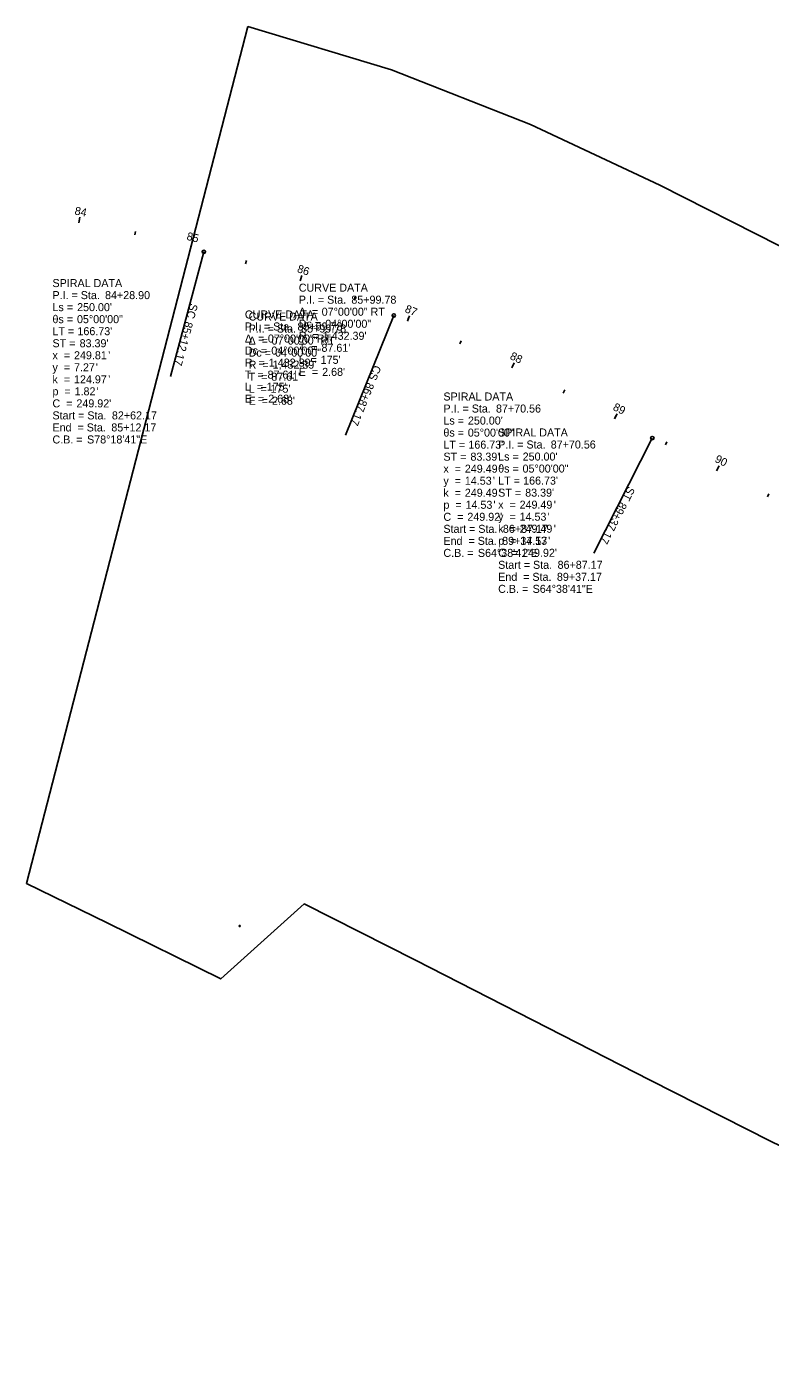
# Model space of a CAD drawing. Extents: x 1999328 to 2003366, y 252318 to 253988.
# Drawn here: x 2001058 to 2001707, y 252318 to 253475 of the extents above; entities that cross this region are included whole.
import ezdxf

# ---------------------------------------------------------------- set-up
doc = ezdxf.new("R2010")
doc.units = 0
for name, color, linetype in [('GE_P_Alignment_500_Stations', 7, 'Continuous'), ('GE_X_Alignment_100_Stations', 7, 'Continuous'), ('RW_X_Esmt_CH', 7, 'Continuous'), ('SC_Scratch3', 7, 'Continuous'), ('SV_X_Mon_Cells_Found', 7, 'Continuous'), ('TX_P_50', 7, 'Continuous'), ('TX_X_20', 7, 'Continuous'), ('TX_X_50', 7, 'Continuous')]:
    doc.layers.add(name, color=color, linetype=linetype)

msp = doc.modelspace()

# ---------------------------------------------------------------- linework, layer by layer
at = {"layer": 'GE_P_Alignment_500_Stations'}
for p, q in [((2001103.3, 253304.2), (2001104.3, 253309.1)), ((2001152.2, 253293.6), (2001152.9, 253296.6)), ((2001212.6, 253278.7), (2001183.4, 253170.1)), ((2001200.8, 253281.8), (2001202.1, 253286.7)), ((2001249, 253268.4), (2001249.8, 253271.3)), ((2001296.6, 253253.4), (2001298.2, 253258.1)), ((2001343.8, 253236.7), (2001344.8, 253239.5)), ((2001378.4, 253223.2), (2001336.2, 253118.9)), ((2001390.3, 253218.3), (2001392.2, 253222.9)), ((2001436.2, 253198.5), (2001437.4, 253201.2)), ((2001481.5, 253177.4), (2001483.7, 253181.9)), ((2001526.4, 253155.5), (2001527.8, 253158.2)), ((2001571.1, 253133), (2001573.4, 253137.5)), ((2001604.2, 253116.2), (2001553.1, 253015.9)), ((2001615.7, 253110.3), (2001617, 253113)), ((2001660.2, 253087.6), (2001662.5, 253092.1)), ((2001704.7, 253064.9), (2001706.1, 253067.6))]:
    msp.add_line(p, q, dxfattribs=at)
for centre in [(2001212.6, 253278.7), (2001378.4, 253223.2), (2001604.2, 253116.2)]:
    msp.add_circle(centre, 1.5, dxfattribs=at)
at = {"layer": 'RW_X_Esmt_CH'}
msp.add_lwpolyline([(2001251, 253475.4), (2001057.7, 252727.4), (2001128.3, 252693.2), (2001227.4, 252644.1), (2001300.1, 252709.6), (2001397.4, 252660.4), (2001499.9, 252608.1), (2001602.3, 252555.9), (2001707.3, 252502.5), (2001828.3, 252444.1), (2001968.2, 252386.2), (2002115.7, 252338.2), (2002180.2, 252318.1), (2002346.8, 253001.2), (2002305.2, 253012.1), (2002211.1, 253042.7), (2002118.4, 253081.1), (2002021.8, 253127.8), (2001920.3, 253179.5), (2001817.9, 253231.7), (2001715.4, 253283.9), (2001610.7, 253336.9), (2001497.9, 253389.8), (2001376.4, 253437.5)], close=True, dxfattribs=at)
at = {"layer": 'SV_X_Mon_Cells_Found'}
for p, q in [((2001212.6, 253278.7), (2001183.4, 253170.1)), ((2001200.8, 253281.8), (2001201.5, 253284.7)), ((2001378.4, 253223.2), (2001336.2, 253118.9)), ((2001604.2, 253116.2), (2001553.1, 253015.9)), ((2001660.2, 253087.6), (2001662.5, 253092.1))]:
    msp.add_line(p, q, dxfattribs=at)
for centre in [(2001212.6, 253278.7), (2001378.4, 253223.2), (2001604.2, 253116.2)]:
    msp.add_circle(centre, 1.5, dxfattribs=at)
at = {"layer": 'TX_P_50'}
for p, q in [((2001103.3, 253304.2), (2001103.9, 253307.1)), ((2001212.6, 253278.7), (2001183.4, 253170.1)), ((2001200.8, 253281.8), (2001202.1, 253286.7)), ((2001296.6, 253253.4), (2001297.6, 253256.2)), ((2001378.4, 253223.2), (2001336.2, 253118.9)), ((2001390.3, 253218.3), (2001391.4, 253221.1)), ((2001481.5, 253177.4), (2001482.8, 253180.1)), ((2001571.1, 253133), (2001572.5, 253135.7)), ((2001604.2, 253116.2), (2001553.1, 253015.9)), ((2001660.2, 253087.6), (2001662.5, 253092.1))]:
    msp.add_line(p, q, dxfattribs=at)
for centre in [(2001212.6, 253278.7), (2001378.4, 253223.2), (2001604.2, 253116.2)]:
    msp.add_circle(centre, 1.5, dxfattribs=at)
at = {"layer": 'TX_X_20'}
msp.add_circle((2001243.9, 252690.3), 0.5, dxfattribs=at)
msp.add_circle((2001243.9, 252690.3), 0.5, dxfattribs=at)

# ---------------------------------------------------------------- texts
at = {"layer": 'GE_P_Alignment_500_Stations'}
for s, rotation, p in [('84', 348.4583, (2001099.3, 253311.5)), ('85', 345.4529, (2001197.1, 253289.4)), ('86', 341.4648, (2001293.5, 253261.2)), ('SC', 254.9781, (2001200.7, 253234.1)), ('87', 337.4779, (2001387.5, 253226.4)), ('85+12.17', 254.9781, (2001196.5, 253218.4)), ('88', 334.4833, (2001479.3, 253185.5)), ('CS', 247.9781, (2001361.2, 253180.4)), ('86+87.17', 247.9781, (2001355.1, 253165.3)), ('89', 333.0886, (2001569.2, 253141.1)), ('90', 332.9781, (2001658.2, 253095.8)), ('ST', 242.9781, (2001583.1, 253074.5)), ('89+37.17', 242.9781, (2001576.2, 253061))]:
    msp.add_text(s, height=7, rotation=rotation, dxfattribs=at).set_placement(p)
at = {"layer": 'GE_X_Alignment_100_Stations'}
for s, p in [('SPIRAL DATA', (2001080.4, 253248)), ('P.I. = Sta. ', (2001080.4, 253237.5)), ('84+28.90', (2001126.3, 253237.5)), ('Ls = ', (2001080.4, 253227)), ("250.00'", (2001101.9, 253227)), ('θs = ', (2001080.4, 253216.5)), ('05°00\'00"', (2001101.8, 253216.5)), ('CURVE DATA', (2001251.7, 253218.8)), ('LT = ', (2001080.4, 253206)), ("166.73'", (2001102.2, 253206)), ('P.I. = Sta. ', (2001251.7, 253208.3)), ('85+99.78', (2001297.6, 253208.3)), ('ST = ', (2001080.4, 253195.5)), ("83.39'", (2001104.1, 253195.5)), ('Δ  = ', (2001251.7, 253197.8)), ('07°00\'00" RT', (2001271.7, 253197.8)), ('x  = ', (2001080.4, 253185)), ('249.81', (2001099.2, 253185)), ("'", (2001129.1, 253185)), ('Dc = ', (2001251.7, 253187.3)), ('04°00\'00"', (2001274.8, 253187.3)), ('y  = ', (2001080.4, 253174.5)), ('7.27', (2001099.2, 253174.5)), ("'", (2001118.2, 253174.5)), ('T  = ', (2001251.7, 253166.3)), ('R  = ', (2001251.7, 253176.8)), ("87.61'", (2001271.5, 253166.3)), ("1,432.39'", (2001272.6, 253176.8)), ('k  = ', (2001080.4, 253164)), ('124.97', (2001099.2, 253164)), ("'", (2001129.1, 253164)), ('L  = ', (2001251.7, 253155.8)), ("175'", (2001270.8, 253155.8)), ('C  = ', (2001080.4, 253143)), ('p  = ', (2001080.4, 253153.5)), ('1.82', (2001099.7, 253153.5)), ("249.92'", (2001101.3, 253143)), ("'", (2001118.7, 253153.5)), ('E  = ', (2001251.7, 253145.3)), ("2.68'", (2001272.1, 253145.3)), ('Start = Sta. ', (2001080.4, 253132.5)), ('82+62.17', (2001132.3, 253132.5)), ('End  = Sta. ', (2001080.4, 253122)), ('85+12.17', (2001131.8, 253122)), ('C.B. = ', (2001080.4, 253111.5)), ('S78°18\'41"E', (2001110.6, 253111.5)), ('SPIRAL DATA', (2001469.6, 253117.6)), ('P.I. = Sta. ', (2001469.6, 253107.1)), ('Ls = ', (2001469.6, 253096.6)), ("250.00'", (2001491, 253096.6)), ('87+70.56', (2001515.5, 253107.1)), ('θs = ', (2001469.6, 253086.1)), ('05°00\'00"', (2001490.9, 253086.1)), ('LT = ', (2001469.6, 253075.6)), ("166.73'", (2001491.4, 253075.6)), ('ST = ', (2001469.6, 253065.1)), ("83.39'", (2001493.2, 253065.1)), ('x  = ', (2001469.6, 253054.6)), ('249.49', (2001488.3, 253054.6)), ("'", (2001518.2, 253054.6)), ('y  = ', (2001469.6, 253044.1)), ('14.53', (2001488.3, 253044.1)), ("'", (2001512.8, 253044.1)), ('k  = ', (2001469.6, 253033.6)), ('249.49', (2001488.3, 253033.6)), ("'", (2001518.2, 253033.6)), ('p  = ', (2001469.6, 253023.1)), ('14.53', (2001488.9, 253023.1)), ("'", (2001513.3, 253023.1)), ('C  = ', (2001469.6, 253012.6)), ("249.92'", (2001490.5, 253012.6)), ('Start = Sta. ', (2001469.6, 253002.1)), ('86+87.17', (2001521.5, 253002.1)), ('C.B. = ', (2001469.6, 252981.1)), ('End  = Sta. ', (2001469.6, 252991.6)), ('S64°38\'41"E', (2001499.7, 252981.1)), ('89+37.17', (2001520.9, 252991.6))]:
    msp.add_text(s, height=7, dxfattribs=at).set_placement(p)
at = {"layer": 'SC_Scratch3'}
for s, p in [('SPIRAL DATA', (2001080.4, 253248)), ('P.I. = Sta. ', (2001080.4, 253237.5)), ('84+28.90', (2001126.3, 253237.5)), ('CURVE DATA', (2001295.5, 253244)), ('Ls = ', (2001080.4, 253227)), ("250.00'", (2001101.9, 253227)), ('P.I. = Sta. ', (2001295.5, 253233.5)), ('85+99.78', (2001341.4, 253233.5)), ('θs = ', (2001080.4, 253216.5)), ('05°00\'00"', (2001101.8, 253216.5)), ('Δ  = ', (2001295.5, 253223)), ('Dc = ', (2001295.5, 253212.5)), ('07°00\'00" RT', (2001315.5, 253223)), ('04°00\'00"', (2001318.6, 253212.5)), ('LT = ', (2001080.4, 253206)), ("166.73'", (2001102.2, 253206)), ('R  = ', (2001295.5, 253202)), ("1,432.39'", (2001316.4, 253202)), ('ST = ', (2001080.4, 253195.5)), ("83.39'", (2001104.1, 253195.5)), ('T  = ', (2001295.5, 253191.5)), ("87.61'", (2001315.3, 253191.5)), ('x  = ', (2001080.4, 253185)), ('249.81', (2001099.2, 253185)), ("'", (2001129.1, 253185)), ('L  = ', (2001295.5, 253181)), ("175'", (2001314.6, 253181)), ('y  = ', (2001080.4, 253174.5)), ('7.27', (2001099.2, 253174.5)), ("'", (2001118.2, 253174.5)), ('E  = ', (2001295.5, 253170.5)), ("2.68'", (2001315.9, 253170.5)), ('k  = ', (2001080.4, 253164)), ('124.97', (2001099.2, 253164)), ("'", (2001129.1, 253164)), ('C  = ', (2001080.4, 253143)), ('p  = ', (2001080.4, 253153.5)), ('1.82', (2001099.7, 253153.5)), ("249.92'", (2001101.3, 253143)), ("'", (2001118.7, 253153.5)), ('Start = Sta. ', (2001080.4, 253132.5)), ('82+62.17', (2001132.3, 253132.5)), ('End  = Sta. ', (2001080.4, 253122)), ('85+12.17', (2001131.8, 253122)), ('C.B. = ', (2001080.4, 253111.5)), ('S78°18\'41"E', (2001110.6, 253111.5)), ('SPIRAL DATA', (2001469.6, 253117.6)), ('P.I. = Sta. ', (2001469.6, 253107.1)), ('Ls = ', (2001469.6, 253096.6)), ("250.00'", (2001491, 253096.6)), ('87+70.56', (2001515.5, 253107.1)), ('θs = ', (2001469.6, 253086.1)), ('05°00\'00"', (2001490.9, 253086.1)), ('LT = ', (2001469.6, 253075.6)), ("166.73'", (2001491.4, 253075.6)), ('ST = ', (2001469.6, 253065.1)), ("83.39'", (2001493.2, 253065.1)), ('x  = ', (2001469.6, 253054.6)), ('249.49', (2001488.3, 253054.6)), ("'", (2001518.2, 253054.6)), ('y  = ', (2001469.6, 253044.1)), ('14.53', (2001488.3, 253044.1)), ("'", (2001512.8, 253044.1)), ('k  = ', (2001469.6, 253033.6)), ('249.49', (2001488.3, 253033.6)), ("'", (2001518.2, 253033.6)), ('p  = ', (2001469.6, 253023.1)), ('14.53', (2001488.9, 253023.1)), ("'", (2001513.3, 253023.1)), ('C  = ', (2001469.6, 253012.6)), ("249.92'", (2001490.5, 253012.6)), ('Start = Sta. ', (2001469.6, 253002.1)), ('86+87.17', (2001521.5, 253002.1)), ('C.B. = ', (2001469.6, 252981.1)), ('End  = Sta. ', (2001469.6, 252991.6)), ('S64°38\'41"E', (2001499.7, 252981.1)), ('89+37.17', (2001520.9, 252991.6))]:
    msp.add_text(s, height=7, dxfattribs=at).set_placement(p)
at = {"layer": 'SV_X_Mon_Cells_Found'}
for s, rotation, p in [('SC', 254.9781, (2001200.7, 253234.1)), ('85+12.17', 254.9781, (2001196.5, 253218.4)), ('CS', 247.9781, (2001361.2, 253180.4)), ('86+87.17', 247.9781, (2001355.1, 253165.3)), ('90', 332.9781, (2001658.2, 253095.8)), ('ST', 242.9781, (2001583.1, 253074.5)), ('89+37.17', 242.9781, (2001576.2, 253061))]:
    msp.add_text(s, height=7, rotation=rotation, dxfattribs=at).set_placement(p)
at = {"layer": 'TX_P_50'}
for s, rotation, p in [('85', 345.4529, (2001197.1, 253289.4)), ('SC', 254.9781, (2001200.7, 253234.1)), ('85+12.17', 254.9781, (2001196.5, 253218.4)), ('CS', 247.9781, (2001361.2, 253180.4)), ('86+87.17', 247.9781, (2001355.1, 253165.3)), ('90', 332.9781, (2001658.2, 253095.8)), ('ST', 242.9781, (2001583.1, 253074.5)), ('89+37.17', 242.9781, (2001576.2, 253061))]:
    msp.add_text(s, height=7, rotation=rotation, dxfattribs=at).set_placement(p)
at = {"layer": 'TX_X_50'}
for s, p in [('SPIRAL DATA', (2001080.4, 253248)), ('P.I. = Sta. ', (2001080.4, 253237.5)), ('84+28.90', (2001126.3, 253237.5)), ('Ls = ', (2001080.4, 253227)), ("250.00'", (2001101.9, 253227)), ('θs = ', (2001080.4, 253216.5)), ('05°00\'00"', (2001101.8, 253216.5)), ('CURVE DATA', (2001248.4, 253220.6)), ('LT = ', (2001080.4, 253206)), ("166.73'", (2001102.2, 253206)), ('P.I. = Sta. ', (2001248.4, 253210.1)), ('85+99.78', (2001294.3, 253210.1)), ('ST = ', (2001080.4, 253195.5)), ("83.39'", (2001104.1, 253195.5)), ('Δ  = ', (2001248.4, 253199.6)), ('Dc = ', (2001248.4, 253189.1)), ('07°00\'00" RT', (2001268.5, 253199.6)), ('04°00\'00"', (2001271.5, 253189.1)), ('x  = ', (2001080.4, 253185)), ('249.81', (2001099.2, 253185)), ("'", (2001129.1, 253185)), ('R  = ', (2001248.4, 253178.6)), ("1,432.39'", (2001269.3, 253178.6)), ('y  = ', (2001080.4, 253174.5)), ('7.27', (2001099.2, 253174.5)), ("'", (2001118.2, 253174.5)), ('T  = ', (2001248.4, 253168.1)), ("87.61'", (2001268.2, 253168.1)), ('k  = ', (2001080.4, 253164)), ('124.97', (2001099.2, 253164)), ("'", (2001129.1, 253164)), ('L  = ', (2001248.4, 253157.6)), ("175'", (2001267.5, 253157.6)), ('C  = ', (2001080.4, 253143)), ('p  = ', (2001080.4, 253153.5)), ('1.82', (2001099.7, 253153.5)), ("249.92'", (2001101.3, 253143)), ("'", (2001118.7, 253153.5)), ('E  = ', (2001248.4, 253147.1)), ("2.68'", (2001268.8, 253147.1)), ('SPIRAL DATA', (2001421.8, 253149)), ('Start = Sta. ', (2001080.4, 253132.5)), ('82+62.17', (2001132.3, 253132.5)), ('P.I. = Sta. ', (2001421.8, 253138.5)), ('87+70.56', (2001467.7, 253138.5)), ('End  = Sta. ', (2001080.4, 253122)), ('85+12.17', (2001131.8, 253122)), ('Ls = ', (2001421.8, 253128)), ("250.00'", (2001443.2, 253128)), ('C.B. = ', (2001080.4, 253111.5)), ('S78°18\'41"E', (2001110.6, 253111.5)), ('θs = ', (2001421.8, 253117.5)), ('05°00\'00"', (2001443.1, 253117.5)), ('ST = ', (2001421.8, 253096.5)), ('LT = ', (2001421.8, 253107)), ("166.73'", (2001443.6, 253107)), ("83.39'", (2001445.4, 253096.5)), ('249.49', (2001440.5, 253086)), ("'", (2001470.4, 253086)), ('y  = ', (2001421.8, 253075.5)), ('x  = ', (2001421.8, 253086)), ('14.53', (2001440.5, 253075.5)), ("'", (2001465, 253075.5)), ('k  = ', (2001421.8, 253065)), ('249.49', (2001440.5, 253065)), ("'", (2001470.4, 253065)), ('p  = ', (2001421.8, 253054.5)), ('14.53', (2001441.1, 253054.5)), ("'", (2001465.5, 253054.5)), ('C  = ', (2001421.8, 253044)), ("249.92'", (2001442.7, 253044)), ('Start = Sta. ', (2001421.8, 253033.5)), ('86+87.17', (2001473.7, 253033.5)), ('End  = Sta. ', (2001421.8, 253023)), ('89+37.17', (2001473.1, 253023)), ('C.B. = ', (2001421.8, 253012.5)), ('S64°38\'41"E', (2001451.9, 253012.5))]:
    msp.add_text(s, height=7, dxfattribs=at).set_placement(p)

doc.saveas('drawing.dxf')
